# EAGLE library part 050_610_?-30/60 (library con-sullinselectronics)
.050 DIP EDGE CARD CONNECTOR .050 [1.27mm] CONTACT CENTERS .610" INSULATEOR HEIGHT Source: .050 DIP EDGE CARD.pdf
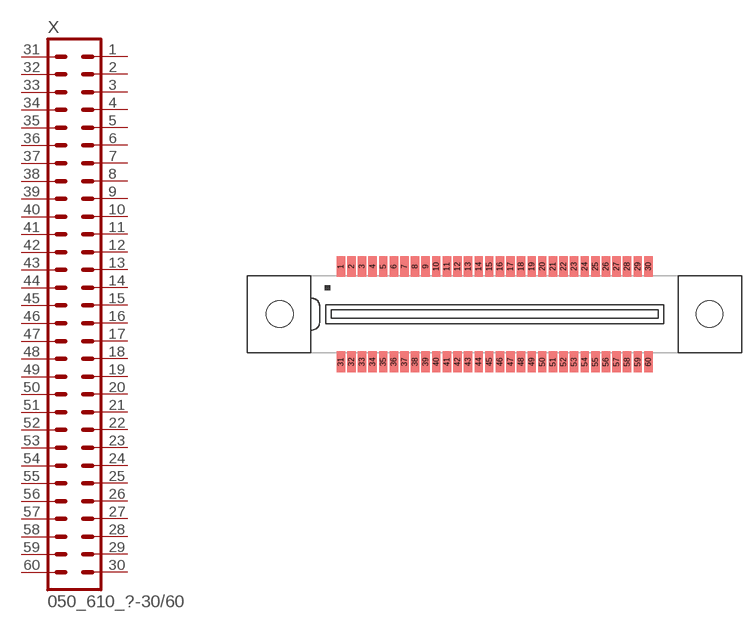
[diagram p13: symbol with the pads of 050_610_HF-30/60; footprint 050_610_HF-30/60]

Designator prefix X

## 050_610_HF-30/60 (OC_FARNELL: unknown; OC_NEWARK: unknown)  [050_610_HF-30/60]
1  1  pas
2  2  pas
3  3  pas
4  4  pas
5  5  pas
6  6  pas
7  7  pas
8  8  pas
9  9  pas
10  10  pas
11  11  pas
12  12  pas
13  13  pas
14  14  pas
15  15  pas
16  16  pas
17  17  pas
18  18  pas
19  19  pas
20  20  pas
21  21  pas
22  22  pas
23  23  pas
24  24  pas
25  25  pas
26  26  pas
27  27  pas
28  28  pas
29  29  pas
30  30  pas
31  31  pas
32  32  pas
33  33  pas
34  34  pas
35  35  pas
36  36  pas
37  37  pas
38  38  pas
39  39  pas
40  40  pas
41  41  pas
42  42  pas
43  43  pas
44  44  pas
45  45  pas
46  46  pas
47  47  pas
48  48  pas
49  49  pas
50  50  pas
51  51  pas
52  52  pas
53  53  pas
54  54  pas
55  55  pas
56  56  pas
57  57  pas
58  58  pas
59  59  pas
60  60  pas

## Footprint 050_610_HF-30/60 (pad centres in mm)
.050 DIP EDGE CARD CONNECTOR SURFACE MOUNT .050 [1.27mm] CONTACT CENTERS .610" INSULATEOR HEIGHT Source: .050 DIP EDGE CARD.pdf
smd 1 x 2.5: 1 -18.415,5.715; 2 -17.145,5.715; 3 -15.875,5.715; 4 -14.605,5.715; 5 -13.335,5.715; 6 -12.065,5.715; 7 -10.795,5.715; 8 -9.525,5.715; 9 -8.255,5.715; 10 -6.985,5.715; 11 -5.715,5.715; 12 -4.445,5.715; 13 -3.175,5.715; 14 -1.905,5.715; 15 -0.635,5.715; 16 0.635,5.715; 17 1.905,5.715; 18 3.175,5.715; 19 4.445,5.715; 20 5.715,5.715; 21 6.985,5.715; 22 8.255,5.715; 23 9.525,5.715; 24 10.795,5.715; 25 12.065,5.715; 26 13.335,5.715; 27 14.605,5.715; 28 15.875,5.715; 29 17.145,5.715; 30 18.415,5.715; 31 -18.415,-5.715; 32 -17.145,-5.715; 33 -15.875,-5.715; 34 -14.605,-5.715; 35 -13.335,-5.715; 36 -12.065,-5.715; 37 -10.795,-5.715; 38 -9.525,-5.715; 39 -8.255,-5.715; 40 -6.985,-5.715; 41 -5.715,-5.715; 42 -4.445,-5.715; 43 -3.175,-5.715; 44 -1.905,-5.715; 45 -0.635,-5.715; 46 0.635,-5.715; 47 1.905,-5.715; 48 3.175,-5.715; 49 4.445,-5.715; 50 5.715,-5.715; 51 6.985,-5.715; 52 8.255,-5.715; 53 9.525,-5.715; 54 10.795,-5.715; 55 12.065,-5.715; 56 13.335,-5.715; 57 14.605,-5.715; 58 15.875,-5.715; 59 17.145,-5.715; 60 18.415,-5.715
hole 3.18 at -25.73,0
hole 3.18 at 25.73,0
